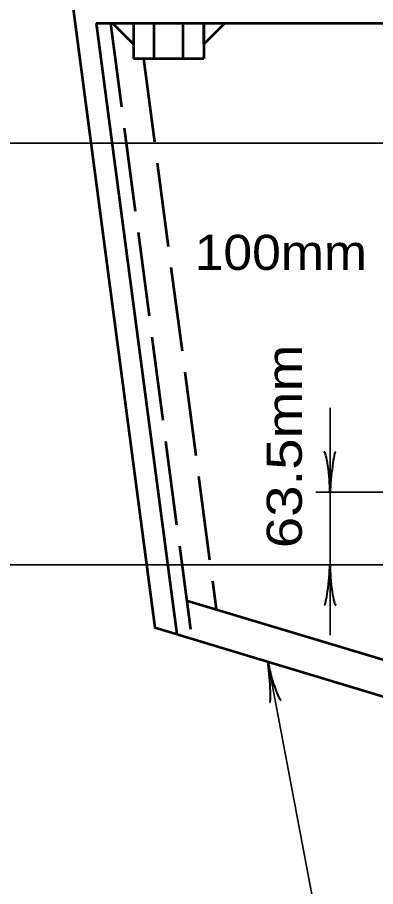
# Model space of a CAD drawing. Extents: x -35 to 821, y -23 to 522.
# Drawn here: x 331.3 to 361.9, y 91.4 to 165.6 of the extents above; entities that cross this region are included whole.
import ezdxf

# ---------------------------------------------------------------- set-up
doc = ezdxf.new("R2010")
doc.units = 0
doc.header["$LTSCALE"] = 1.2
doc.linetypes.add('LONG_DASHED', pattern=[7.5, 6, -1.5])
doc.linetypes.add('SHORT_DASHED', pattern=[2.7, 1.5, -1.2])
doc.layers.add('1', color=7, linetype='Continuous', lineweight=35)

msp = doc.modelspace()

# ---------------------------------------------------------------- linework, layer by layer
at = {"layer": '1', "linetype": 'SHORT_DASHED', "lineweight": 53}
for p, q in [((342.674, 171.42), (342.674, 165.12)), ((345.745, 171.42), (345.745, 165.12))]:
    msp.add_line(p, q, dxfattribs=at)
at = {"layer": '1', "lineweight": 53}
for p, q in [((338.056, 165.12), (344.935, 112.95)), ((341.245, 163.32), (339.445, 165.12)), ((341.245, 165.12), (341.245, 162.12)), ((342.974, 165.12), (342.974, 162.12)), ((345.445, 165.12), (345.445, 162.12)), ((347.245, 165.12), (347.245, 162.12)), ((347.245, 165.12), (367.874, 165.12)), ((341.245, 162.12), (347.245, 162.12)), ((345.766, 115.833), (377.845, 106.154))]:
    msp.add_line(p, q, dxfattribs=at)
at = {"layer": '1', "linetype": 'LONG_DASHED', "lineweight": 53}
for p, q in [((339.266, 165.12), (346.196, 112.57)), ((342.082, 162.12), (348.287, 115.072))]:
    msp.add_line(p, q, dxfattribs=at)
at = {"layer": '1'}
for p, q in [((367.025, 154.876), (322.625, 154.876)), ((380.245, 125.066), (356.812, 125.066)), ((367.025, 118.876), (322.625, 118.876))]:
    msp.add_line(p, q, dxfattribs=at)
at = {"layer": '1', "lineweight": 53}
for points in [[(377.845, 168.12), (335.845, 168.12), (343.045, 113.52), (377.845, 103.02)], [(338.04, 165.12), (339.445, 165.12), (347.245, 165.12)], [(339.266, 165.12), (341.245, 165.12), (341.245, 163.32)]]:
    msp.add_lwpolyline(points, dxfattribs=at)
msp.add_lwpolyline([(347.245, 163.32), (347.245, 165.12), (349.045, 165.12)], close=True, dxfattribs=at)
at = {"layer": '1'}
for points in [[(358.012, 132.266), (358.012, 125.066), (358.012, 118.876), (358.012, 112.876)], [(352.697, 110.608), (357.189, 86.826), (366.131, 86.826)]]:
    msp.add_lwpolyline(points, dxfattribs=at)
at = {"layer": '1', "lineweight": 40}
for centre, major_axis, ratio, start_param, end_param in [((357.68, 126.375), (0.187, -2.143), 0.122415, 0.896353, 3.141593), ((357.68, 126.375), (0.187, -2.143), 0.122415, 0.896353, 3.141593), ((358.265, 126.411), (-0.211, -2.108), 0.07063, 3.140715, 5.41811), ((358.265, 126.411), (-0.211, -2.108), 0.07063, 3.140715, 5.41811), ((357.758, 117.531), (0.211, 2.108), 0.07063, 3.140715, 5.41811), ((358.343, 117.567), (-0.187, 2.143), 0.122415, 0.896353, 3.141593), ((352.697, 109.24), (-0.184, 2.11), 0.07063, 3.140715, 5.41811), ((352.697, 109.24), (-0.184, 2.11), 0.07063, 3.140715, 5.41811), ((353.266, 109.383), (-0.582, 2.071), 0.122415, 0.896353, 3.141593), ((353.266, 109.383), (-0.582, 2.071), 0.122415, 0.896353, 3.141593)]:
    msp.add_ellipse(centre, major_axis=major_axis, ratio=ratio, start_param=start_param, end_param=end_param, dxfattribs=at)

# ---------------------------------------------------------------- texts
at = {"layer": '1', "width": 1.1}
msp.add_text('100mm', height=3, dxfattribs=at).set_placement((346.453, 144.052))
at = {"layer": '1', "width": 1.2}
msp.add_text('63.5mm', height=3, rotation=90, dxfattribs=at).set_placement((355.608, 120.293))

doc.saveas('drawing.dxf')
